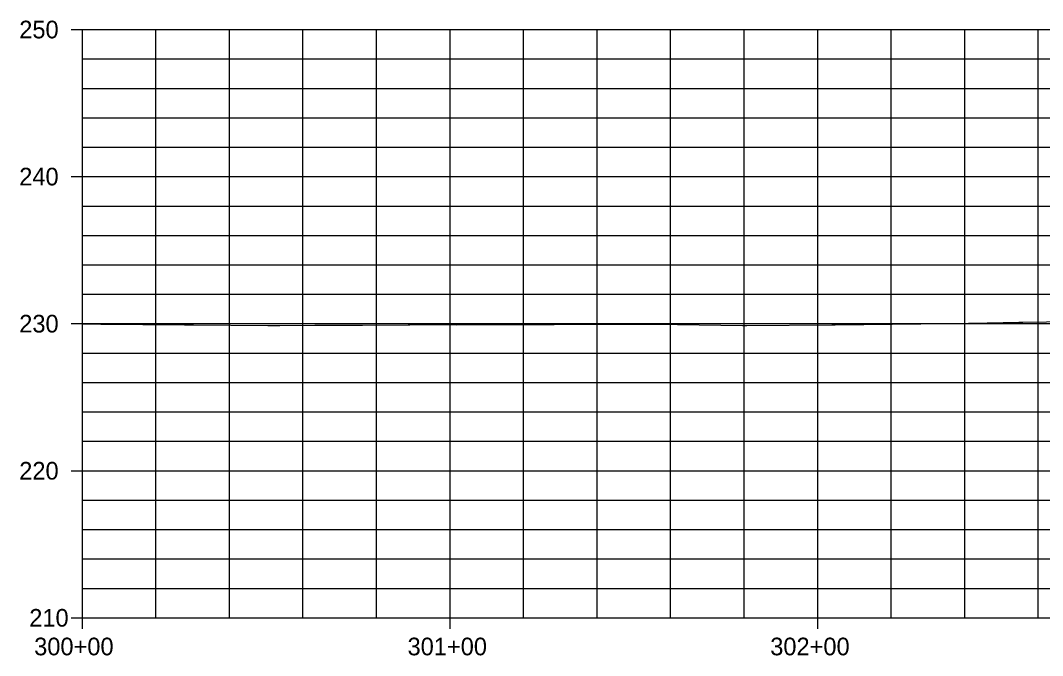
# Model space of a CAD drawing. Extents: x 1811793 to 1813336, y 532176 to 533566.
# Drawn here: x 1811997.4 to 1812275.4, y 532897.6 to 533070.4 of the extents above; entities that cross this region are included whole.
import ezdxf

# ---------------------------------------------------------------- set-up
doc = ezdxf.new("R2010")
doc.units = 0
for name, color, linetype in [('R_Axis', 7, 'Continuous'), ('R_Axis Annot', 7, 'Continuous'), ('R_Exist Surface', 7, 'Continuous'), ('R_Grid', 7, 'Continuous')]:
    doc.layers.add(name, color=color, linetype=linetype)

msp = doc.modelspace()

# ---------------------------------------------------------------- linework, layer by layer
at = {"layer": 'R_Axis'}
for q in [(1812014.24, 533067.89), (1813014.24, 532907.89)]:
    msp.add_line((1812014.24, 532907.89), q, dxfattribs=at)
at = {"layer": 'R_Exist Surface'}
msp.add_lwpolyline([(1812014.24, 532987.81), (1812019.25, 532987.79), (1812019.33, 532987.79), (1812042.01, 532987.6), (1812044.51, 532987.57), (1812064.7, 532987.4), (1812064.77, 532987.4), (1812067.94, 532987.42), (1812077.49, 532987.46), (1812077.61, 532987.46), (1812090.18, 532987.51), (1812090.44, 532987.51), (1812102.86, 532987.57), (1812103.27, 532987.56), (1812115.54, 532987.62), (1812116.1, 532987.61), (1812128.74, 532987.65), (1812129.34, 532987.65), (1812141.98, 532987.68), (1812142.59, 532987.68), (1812155.21, 532987.71), (1812155.83, 532987.71), (1812168.45, 532987.75), (1812169.08, 532987.75), (1812170.25, 532987.73), (1812193.8, 532987.35), (1812194.98, 532987.35), (1812218.06, 532987.6), (1812219.02, 532987.6), (1812242.33, 532987.85), (1812255.25, 532988.05), (1812256.1, 532988.06), (1812268.98, 532988.26), (1812270.02, 532988.28), (1812282.86, 532988.48)], dxfattribs=at)
at = {"layer": 'R_Grid'}
for p, q in [((1812011.24, 533067.89), (1812014.24, 533067.89)), ((1812011.24, 533067.89), (1812014.24, 533067.89)), ((1812014.24, 533067.89), (1813014.24, 533067.89)), ((1812014.24, 533067.89), (1813014.24, 533067.89)), ((1812034.24, 532907.89), (1812034.24, 533067.89)), ((1812054.24, 532907.89), (1812054.24, 533067.89)), ((1812074.24, 532907.89), (1812074.24, 533067.89)), ((1812094.24, 532907.89), (1812094.24, 533067.89)), ((1812114.24, 532907.89), (1812114.24, 533067.89)), ((1812134.24, 532907.89), (1812134.24, 533067.89)), ((1812154.24, 532907.89), (1812154.24, 533067.89)), ((1812174.24, 532907.89), (1812174.24, 533067.89)), ((1812194.24, 532907.89), (1812194.24, 533067.89)), ((1812214.24, 532907.89), (1812214.24, 533067.89)), ((1812234.24, 532907.89), (1812234.24, 533067.89)), ((1812254.24, 532907.89), (1812254.24, 533067.89)), ((1812274.24, 532907.89), (1812274.24, 533067.89)), ((1812014.24, 533059.89), (1812015.74, 533059.89)), ((1812014.24, 533059.89), (1813014.24, 533059.89)), ((1812014.24, 533051.89), (1812015.74, 533051.89)), ((1812014.24, 533051.89), (1813014.24, 533051.89)), ((1812014.24, 533043.89), (1812015.74, 533043.89)), ((1812014.24, 533043.89), (1813014.24, 533043.89)), ((1812014.24, 533035.89), (1812015.74, 533035.89)), ((1812014.24, 533035.89), (1813014.24, 533035.89)), ((1812011.24, 533027.89), (1812014.24, 533027.89)), ((1812014.24, 533027.89), (1813014.24, 533027.89)), ((1812014.24, 533019.89), (1812015.74, 533019.89)), ((1812014.24, 533019.89), (1813014.24, 533019.89)), ((1812014.24, 533011.89), (1812015.74, 533011.89)), ((1812014.24, 533011.89), (1813014.24, 533011.89)), ((1812014.24, 533003.89), (1812015.74, 533003.89)), ((1812014.24, 533003.89), (1813014.24, 533003.89)), ((1812014.24, 532995.89), (1812015.74, 532995.89)), ((1812014.24, 532995.89), (1813014.24, 532995.89)), ((1812011.24, 532987.89), (1812014.24, 532987.89)), ((1812014.24, 532987.89), (1813014.24, 532987.89)), ((1812014.24, 532979.89), (1812015.74, 532979.89)), ((1812014.24, 532979.89), (1813014.24, 532979.89)), ((1812014.24, 532971.89), (1812015.74, 532971.89)), ((1812014.24, 532971.89), (1813014.24, 532971.89)), ((1812014.24, 532963.89), (1812015.74, 532963.89)), ((1812014.24, 532963.89), (1813014.24, 532963.89)), ((1812014.24, 532955.89), (1812015.74, 532955.89)), ((1812014.24, 532955.89), (1813014.24, 532955.89)), ((1812011.24, 532947.89), (1812014.24, 532947.89)), ((1812014.24, 532947.89), (1813014.24, 532947.89)), ((1812014.24, 532939.89), (1812015.74, 532939.89)), ((1812014.24, 532939.89), (1813014.24, 532939.89)), ((1812014.24, 532931.89), (1812015.74, 532931.89)), ((1812014.24, 532931.89), (1813014.24, 532931.89)), ((1812014.24, 532923.89), (1812015.74, 532923.89)), ((1812014.24, 532923.89), (1813014.24, 532923.89)), ((1812014.24, 532915.89), (1812015.74, 532915.89)), ((1812014.24, 532915.89), (1813014.24, 532915.89)), ((1812011.24, 532907.89), (1812014.24, 532907.89)), ((1812014.24, 532904.89), (1812014.24, 532907.89)), ((1812114.24, 532904.89), (1812114.24, 532907.89)), ((1812214.24, 532904.89), (1812214.24, 532907.89))]:
    msp.add_line(p, q, dxfattribs=at)

# ---------------------------------------------------------------- texts
at = {"layer": 'R_Axis Annot'}
for s, height, p in [('250', 4.8, (1811997.08, 533065.49)), ('240', 4.8, (1811997.08, 533025.49)), ('230', 4.8, (1811997.08, 532985.49)), ('220', 4.8, (1811997.08, 532945.49)), ('210', 4.8, (1811999.8, 532905.49)), ('-', 0.0001, (1812014.24, 532907.89)), ('300+00', 4.8, (1812001.14, 532897.69)), ('301+00', 4.8, (1812102.69, 532897.69)), ('302+00', 4.8, (1812201.33, 532897.69))]:
    msp.add_text(s, height=height, dxfattribs=at).set_placement(p)

doc.saveas('drawing.dxf')
